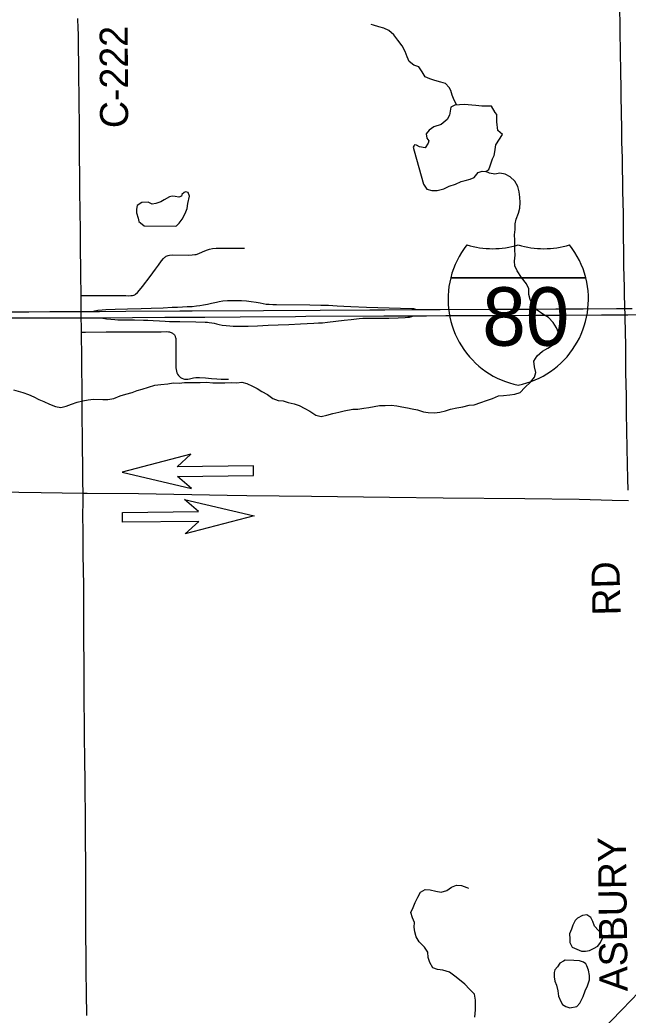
# Model space of a CAD drawing. Extents: x 0 to 34, y 0 to 22.
# Drawn here: x 10.62 to 13.7, y 14.41 to 19.45 of the extents above; entities that cross this region are included whole.
import ezdxf

# ---------------------------------------------------------------- set-up
doc = ezdxf.new("R2010")
doc.units = 0
for name, color, linetype in [('GM_X_County_Road', 7, 'Continuous'), ('GM_X_County_Road_Text', 7, 'Continuous'), ('GM_X_Interchange_Ramps', 7, 'Continuous'), ('GM_X_Interstate_Location', 7, 'Continuous'), ('GM_X_Interstate_Route', 7, 'Continuous'), ('GM_X_Interstate_Shield', 7, 'Continuous'), ('GM_X_Minor_Lake', 7, 'Continuous'), ('GM_X_Minor_River', 7, 'Continuous'), ('GM_X_State_Route', 7, 'Continuous'), ('GM_X_Township_Road', 7, 'Continuous'), ('PM_P_Cells', 7, 'Continuous')]:
    doc.layers.add(name, color=color, linetype=linetype)

msp = doc.modelspace()

# ---------------------------------------------------------------- linework, layer by layer
at = {"layer": 'GM_X_County_Road'}
for points in [[(13.7009, 17.0659), (13.6992, 17.1249), (13.6975, 17.1964), (13.6959, 17.2803), (13.6929, 17.4559), (13.6922, 17.5442), (13.6914, 17.6031), (13.6899, 17.6622), (13.6897, 17.7445), (13.6888, 17.7786), (13.6873, 17.8873), (13.6866, 17.9199), (13.6859, 17.9541), (13.6857, 17.9603), (13.6852, 17.9863), (13.6849, 18.0022), (13.6833, 18.0519), (13.6824, 18.0923), (13.6814, 18.1482), (13.6799, 18.2009), (13.6787, 18.246), (13.6776, 18.3797), (13.6769, 18.4667), (13.6743, 18.5801), (13.674, 18.636), (13.6724, 18.6872), (13.672, 18.7463), (13.6699, 18.8286), (13.6689, 18.883), (13.6668, 18.9902), (13.666, 19.0492), (13.6655, 19.0958), (13.6646, 19.189), (13.6623, 19.2806), (13.6605, 19.3909), (13.6595, 19.5338)], [(10.9342, 18.0514), (10.934, 18.0863), (10.9331, 18.1235), (10.9326, 18.1841), (10.9317, 18.2882), (10.9314, 18.3348), (10.9307, 18.4014), (10.9297, 18.4588), (10.9294, 18.4882), (10.9285, 18.5689), (10.9271, 18.6634), (10.9266, 18.7504), (10.9256, 18.8359), (10.9254, 18.8887), (10.9253, 18.9291), (10.9246, 19.013), (10.9236, 19.0876), (10.923, 19.1311), (10.9231, 19.1899), (10.9223, 19.2379), (10.9218, 19.2907), (10.9214, 19.3372), (10.9206, 19.3744), (10.9198, 19.4039), (10.9181, 19.4536)], [(10.9357, 17.8662), (10.9354, 17.8905), (10.9349, 17.9388), (10.9347, 17.971), (10.9346, 17.9884), (10.9342, 18.0514)], [(10.944, 17.0515), (10.9433, 17.1095), (10.9422, 17.198), (10.9415, 17.274), (10.9407, 17.3439), (10.9402, 17.4262), (10.9397, 17.4712), (10.9395, 17.5412), (10.9389, 17.6002), (10.9381, 17.667), (10.9375, 17.7183), (10.9371, 17.7617), (10.9362, 17.8361), (10.9357, 17.8662)], [(10.9629, 14.4078), (10.9624, 14.4295), (10.9615, 14.4978), (10.9611, 14.5475), (10.9605, 14.605), (10.9602, 14.6765), (10.9595, 14.7355), (10.9589, 14.7883), (10.9587, 14.8458), (10.9583, 14.9017), (10.9579, 14.9561), (10.9582, 15.0214), (10.9575, 15.11), (10.9576, 15.1628), (10.9576, 15.1876), (10.9565, 15.2839), (10.9563, 15.3477), (10.9562, 15.4362), (10.9548, 15.5341), (10.9542, 15.5963), (10.953, 15.6957), (10.9523, 15.7469), (10.9519, 15.7765), (10.9517, 15.8293), (10.9515, 15.8898), (10.9504, 15.9923), (10.9499, 16.0405), (10.9497, 16.1058), (10.9491, 16.2037), (10.9482, 16.2938), (10.948, 16.3637), (10.948, 16.4632), (10.9475, 16.5238), (10.9474, 16.5906), (10.946, 16.6558), (10.9454, 16.7459), (10.9451, 16.791), (10.9443, 16.8531), (10.9436, 16.9417), (10.9439, 17.0054), (10.944, 17.0515)]]:
    msp.add_lwpolyline(points, dxfattribs=at)
at = {"layer": 'GM_X_Interchange_Ramps'}
for points in [[(10.993, 17.9713), (11.0035, 17.9742), (11.0184, 17.9775), (11.0399, 17.9798), (11.059, 17.9812), (11.1057, 17.9825), (11.1693, 17.9842), (11.2372, 17.986), (11.2886, 17.9873), (11.3494, 17.99), (11.3951, 17.9919), (11.4215, 17.993), (11.4478, 17.9941), (11.4711, 17.9951), (11.4953, 17.9966), (11.5184, 17.9991), (11.5352, 18.0012), (11.5534, 18.0046), (11.5733, 18.0085), (11.5943, 18.013), (11.6185, 18.0183), (11.6324, 18.0214), (11.6503, 18.0238), (11.6741, 18.0256), (11.709, 18.0255), (11.7447, 18.0259), (11.7713, 18.0246), (11.7947, 18.0217), (11.8192, 18.0181), (11.8399, 18.0143), (11.8553, 18.0111), (11.8703, 18.0083), (11.886, 18.0069), (11.9035, 18.0062), (11.922, 18.006), (12.0913, 18.0047), (12.1472, 18.0035), (12.1847, 18.0022), (12.2294, 18.0001), (12.2635, 17.9982), (12.2992, 17.9962), (12.3784, 17.9928), (12.6064, 17.9865), (12.6114, 17.9861), (12.6153, 17.9855), (12.6198, 17.9844), (12.6255, 17.9828), (12.633, 17.9804)], [(11.0299, 17.9393), (11.0445, 17.9369), (11.0634, 17.9338), (11.0845, 17.9312), (11.1042, 17.9297), (11.1201, 17.9291), (11.1549, 17.9285), (11.2037, 17.9285), (11.2504, 17.9275), (11.2722, 17.9267), (11.2979, 17.9253), (11.3299, 17.9237), (11.3595, 17.9219), (11.3819, 17.9207), (11.4332, 17.9193), (11.5151, 17.918), (11.5613, 17.9167), (11.5727, 17.9159), (11.5815, 17.9151), (11.595, 17.913), (11.6072, 17.9109), (11.6184, 17.9083), (11.6327, 17.9052), (11.648, 17.9021), (11.6672, 17.8995), (11.6857, 17.8974), (11.7025, 17.8966), (11.7257, 17.8961), (11.7794, 17.8972), (11.8267, 17.8987), (11.8798, 17.9006), (11.9313, 17.9027), (11.9843, 17.9052), (12.0438, 17.9082), (12.1108, 17.9115), (12.1352, 17.9127), (12.1557, 17.914), (12.1804, 17.9161), (12.2654, 17.9263), (12.3009, 17.9303), (12.3409, 17.9347), (12.3591, 17.9363), (12.3721, 17.9368), (12.4006, 17.9371), (12.4248, 17.9372), (12.491, 17.9375), (12.5375, 17.9383), (12.5736, 17.9395), (12.5871, 17.9413), (12.5947, 17.9426), (12.6063, 17.946), (12.6156, 17.9487)]]:
    msp.add_lwpolyline(points, dxfattribs=at)
at = {"layer": 'GM_X_Interstate_Route'}
for points in [[(10.993, 17.9713), (11.0277, 17.9714), (11.1602, 17.9721), (11.433, 17.9736), (11.4964, 17.974), (11.8565, 17.9756), (12.1428, 17.9778), (12.3942, 17.9792), (12.4711, 17.9796), (12.633, 17.9804), (12.7495, 17.9804), (13.0075, 17.9818), (13.1481, 17.9825), (13.2237, 17.983), (13.3355, 17.9838), (13.4734, 17.9847), (13.6416, 17.9859), (13.6852, 17.9863), (13.7215, 17.9865)], [(7.4719, 17.9218), (7.5489, 17.9221), (7.6598, 17.9224), (7.7361, 17.9227), (8.0027, 17.9242), (8.0905, 17.9246), (8.2781, 17.9264), (8.3517, 17.9271), (8.5716, 17.9273), (8.9286, 17.9295), (9.0917, 17.9306), (9.2471, 17.9311), (9.406, 17.9317), (9.5726, 17.9321), (9.6848, 17.9327), (9.6918, 17.9328), (9.9166, 17.9339), (10.4286, 17.9381), (10.7084, 17.9392), (10.9328, 17.9387), (10.9349, 17.9388), (11.0299, 17.9393)], [(10.4796, 17.9683), (10.6702, 17.9694), (10.7762, 17.9701), (10.8983, 17.9708), (10.9347, 17.971), (10.993, 17.9713)], [(11.0299, 17.9393), (11.3584, 17.9414), (11.5599, 17.9427), (11.7385, 17.9439), (12.0183, 17.9459), (12.0715, 17.9463), (12.4647, 17.9481), (12.6156, 17.9487), (12.6805, 17.9488), (12.7784, 17.9497), (13.0435, 17.9511), (13.1956, 17.952), (13.3815, 17.9528), (13.5668, 17.9536), (13.6859, 17.9541), (13.7002, 17.9542), (13.8218, 17.9548)]]:
    msp.add_lwpolyline(points, dxfattribs=at)
at = {"layer": 'GM_X_Interstate_Shield'}
for p, q in [((12.8036, 18.1413), (13.4868, 18.1413)), ((13.4868, 18.1413), (12.8036, 18.1413)), ((13.4868, 18.1413), (12.8036, 18.1413))]:
    msp.add_line(p, q, dxfattribs=at)
for centre, start, end in [((13.234, 18.0325), 141.669, 165.8066), ((13.0155, 18.7323), 253.0091, 286.9909), ((13.2749, 18.7323), 253.0091, 286.9909), ((13.0564, 18.0325), 14.1934, 38.331), ((13.234, 18.0325), 165.8066, 258.463), ((13.0564, 18.0325), 281.537, 14.1934)]:
    msp.add_arc(centre, 0.4439, start, end, dxfattribs=at)
at = {"layer": 'GM_X_Minor_Lake'}
for p, q in [((12.6193, 18.7845), (12.6657, 18.6151)), ((11.2524, 18.4039), (11.4096, 18.4029)), ((13.4186, 14.7531), (13.4652, 14.7328)), ((13.4269, 14.6849), (13.3824, 14.6872))]:
    msp.add_line(p, q, dxfattribs=at)
for points in [[(12.6657, 18.6151), (12.683, 18.5897), (12.7077, 18.5833), (12.7351, 18.5827), (12.7691, 18.5917), (12.7964, 18.6053), (12.8285, 18.6151), (12.8568, 18.6288), (12.8775, 18.6337), (12.9021, 18.6397), (12.9219, 18.6494), (12.9424, 18.6734), (12.9632, 18.6803), (12.9812, 18.6786), (12.9972, 18.6902), (13.0036, 18.7074), (13.0155, 18.7426), (13.0229, 18.7598), (13.0265, 18.7788), (13.0318, 18.814), (13.0662, 18.8667), (13.0423, 18.8873), (13.0362, 18.9299), (13.0377, 18.967), (13.029, 18.9773), (13.0107, 19.0103), (12.9605, 19.0107), (12.9302, 19.0132), (12.8723, 19.0182), (12.8241, 19.0148), (12.8043, 19.0051), (12.7981, 18.9651), (12.7851, 18.9422), (12.7551, 18.9171), (12.7183, 18.9053), (12.6948, 18.888), (12.6799, 18.8697), (12.683, 18.8479), (12.6935, 18.8348), (12.6899, 18.8224), (12.675, 18.7994), (12.6456, 18.8048), (12.6303, 18.8131), (12.6208, 18.814), (12.618, 18.8111), (12.6134, 18.8016), (12.6193, 18.7845)], [(11.4096, 18.4029), (11.4162, 18.4049), (11.4303, 18.4183), (11.4452, 18.4375), (11.461, 18.4671), (11.4711, 18.4928), (11.4746, 18.5176), (11.4818, 18.5537), (11.4749, 18.5736), (11.4626, 18.5763), (11.4551, 18.5734), (11.4438, 18.5628), (11.442, 18.5552), (11.4288, 18.5493), (11.4098, 18.5529), (11.3956, 18.5537), (11.3814, 18.5516), (11.3541, 18.5361), (11.3382, 18.5264), (11.3127, 18.5166), (11.2928, 18.5145), (11.2729, 18.5237), (11.2407, 18.5224), (11.2172, 18.5079), (11.2145, 18.4889), (11.2147, 18.4708), (11.2226, 18.4434), (11.2266, 18.4263), (11.2352, 18.4188), (11.2524, 18.4039)], [(13.4652, 14.7328), (13.4861, 14.7321), (13.505, 14.7361), (13.5266, 14.7458), (13.5473, 14.7575), (13.5613, 14.7766), (13.5724, 14.8014), (13.5665, 14.8222), (13.5512, 14.8373), (13.531, 14.8598), (13.5232, 14.8834), (13.5116, 14.9033), (13.4916, 14.9163), (13.4699, 14.9132), (13.4454, 14.9006), (13.4332, 14.8881), (13.4221, 14.8652), (13.4148, 14.8442), (13.4037, 14.8203), (13.4068, 14.7947), (13.407, 14.7767), (13.4186, 14.7531)], [(13.3824, 14.6872), (13.3739, 14.6823), (13.3551, 14.6726), (13.344, 14.6535), (13.3299, 14.6381), (13.3263, 14.6248), (13.3265, 14.603), (13.3296, 14.5802), (13.3384, 14.5604), (13.3463, 14.532), (13.3484, 14.5054), (13.3601, 14.4781), (13.3688, 14.462), (13.386, 14.4527), (13.4059, 14.4463), (13.4409, 14.4524), (13.4568, 14.4697), (13.4744, 14.5031), (13.4835, 14.5327), (13.4956, 14.5565), (13.5057, 14.587), (13.5054, 14.6089), (13.5004, 14.6373), (13.4926, 14.659), (13.4877, 14.6685), (13.4753, 14.6778), (13.4554, 14.6842), (13.4269, 14.6849)]]:
    msp.add_lwpolyline(points, dxfattribs=at)
at = {"layer": 'GM_X_Minor_River'}
for points in [[(12.7966, 19.1047), (12.7777, 19.1241), (12.753, 19.1316), (12.7236, 19.1391), (12.6979, 19.1484), (12.6741, 19.1588), (12.6598, 19.1843), (12.6426, 19.209), (12.6179, 19.2183), (12.5932, 19.2363), (12.5826, 19.26), (12.573, 19.2875), (12.5577, 19.3159), (12.5357, 19.3434), (12.5157, 19.3718), (12.49, 19.3925), (12.4662, 19.4048), (12.4396, 19.4122), (12.4139, 19.4197), (12.4016, 19.4234)], [(12.8341, 19.0155), (12.821, 19.0404), (12.8112, 19.065), (12.8043, 19.0896), (12.7966, 19.1047)], [(11.9554, 17.5178), (11.981, 17.5105), (12.0123, 17.5033), (12.037, 17.4941), (12.0666, 17.4802), (12.0904, 17.4653), (12.1219, 17.4457), (12.1484, 17.4394), (12.1768, 17.4464), (12.207, 17.4543), (12.2372, 17.4613), (12.2646, 17.4673), (12.3081, 17.4764), (12.3336, 17.4767), (12.3648, 17.4808), (12.3903, 17.484), (12.4158, 17.49), (12.4433, 17.4941), (12.4716, 17.4954), (12.5029, 17.4967), (12.5304, 17.4923), (12.5569, 17.4878), (12.5845, 17.4834), (12.6082, 17.478), (12.6357, 17.4736), (12.6652, 17.4635), (12.6889, 17.4599), (12.7211, 17.4584), (12.7485, 17.4616), (12.7778, 17.4676), (12.8033, 17.4765), (12.8344, 17.4825), (12.8656, 17.4876), (12.8977, 17.4966), (12.9223, 17.4978), (12.9553, 17.5096), (12.9846, 17.5194), (13.0148, 17.5302), (13.0459, 17.5429), (13.0714, 17.5461), (13.1026, 17.5493), (13.1281, 17.5524), (13.1546, 17.5603), (13.178, 17.5862), (13.207, 17.6132), (13.2276, 17.6381), (13.2349, 17.6619), (13.227, 17.6912), (13.2238, 17.7197), (13.2415, 17.7465), (13.2687, 17.7705), (13.295, 17.7851), (13.3232, 17.8044), (13.3457, 17.8293), (13.352, 17.8551), (13.3384, 17.8872), (13.3211, 17.9154), (13.299, 17.9399), (13.2704, 17.9576), (13.2408, 17.9772), (13.2169, 18.0044), (13.2052, 18.0309), (13.1983, 18.0564), (13.1989, 18.0859), (13.1863, 18.1114), (13.1623, 18.1424), (13.1392, 18.1763), (13.1276, 18.2018), (13.1264, 18.2255), (13.1289, 18.2559), (13.1286, 18.2825), (13.1274, 18.3072), (13.128, 18.3319), (13.1268, 18.3585), (13.1293, 18.3851), (13.13, 18.4136), (13.1354, 18.4374), (13.1464, 18.4688), (13.1537, 18.4936), (13.1553, 18.523), (13.1531, 18.5487), (13.1499, 18.5771), (13.143, 18.6036), (13.1285, 18.631), (13.1046, 18.6516), (13.0798, 18.6665), (13.0523, 18.67), (13.0268, 18.6659), (12.9993, 18.6703), (12.9812, 18.6786)], [(10.5922, 17.5738), (10.6396, 17.5611), (10.6682, 17.551), (10.6948, 17.538), (10.7205, 17.526), (10.7462, 17.5149), (10.7748, 17.501), (10.8052, 17.4899), (10.8318, 17.4855), (10.8582, 17.4906), (10.8856, 17.5013), (10.9138, 17.5112), (10.9422, 17.5191), (10.9696, 17.5242), (10.997, 17.5264), (11.0434, 17.526), (11.0699, 17.5244), (11.0992, 17.5295), (11.1313, 17.5432), (11.1605, 17.5521), (11.1917, 17.561), (11.2181, 17.5708), (11.2426, 17.5777), (11.2757, 17.5876), (11.3077, 17.5985), (11.3371, 17.6017), (11.3721, 17.604), (11.4004, 17.609), (11.4298, 17.6075), (11.4572, 17.6116), (11.4818, 17.611), (11.5358, 17.6116), (11.568, 17.6129), (11.6002, 17.6095), (11.6258, 17.6098), (11.6617, 17.6093), (11.6949, 17.6106), (11.7224, 17.6091), (11.7479, 17.6132), (11.7726, 17.6068), (11.8011, 17.5919), (11.8249, 17.5808), (11.8488, 17.5659), (11.8773, 17.5501), (11.9041, 17.5305), (11.9307, 17.5194), (11.9554, 17.5178)], [(12.9254, 14.398), (12.9288, 14.435), (12.9283, 14.4853), (12.9232, 14.5147), (12.8992, 14.541), (12.8753, 14.5654), (12.8476, 14.5879), (12.8237, 14.6066), (12.797, 14.6272), (12.7637, 14.6372), (12.7372, 14.6398), (12.7134, 14.649), (12.6989, 14.6754), (12.6892, 14.7), (12.6879, 14.7275), (12.6706, 14.7529), (12.6447, 14.7802), (12.6293, 14.8056), (12.6214, 14.8302), (12.6193, 14.8539), (12.62, 14.8776), (12.6112, 14.9022), (12.6024, 14.9287), (12.6144, 14.9535), (12.6245, 14.9783), (12.6375, 15.006), (12.6505, 15.0309), (12.6749, 15.0444), (12.7005, 15.0428), (12.729, 15.0365), (12.7556, 15.0321), (12.7839, 15.04), (12.8083, 15.0564), (12.8328, 15.0662), (12.8584, 15.0646), (12.885, 15.0554), (12.8936, 15.0518)]]:
    msp.add_lwpolyline(points, dxfattribs=at)
at = {"layer": 'GM_X_State_Route'}
for points in [[(10.3908, 17.0589), (10.7326, 17.0543), (10.944, 17.0515), (10.9641, 17.0512), (11.2251, 17.0488), (11.6738, 17.0415), (11.7717, 17.0395), (12.0995, 17.036), (12.4942, 17.0313), (12.7661, 17.0273), (13.178, 17.0239), (13.453, 17.02), (13.6208, 17.016), (13.7026, 17.0131)], [(13.4993, 14.2609), (13.671, 14.4383), (13.7555, 14.5258), (13.9625, 14.7401), (14.2036, 14.9913), (14.4144, 15.2089), (14.5928, 15.3952), (14.8657, 15.678), (15.0774, 15.897), (15.1208, 15.9421)]]:
    msp.add_lwpolyline(points, dxfattribs=at)
at = {"layer": 'GM_X_Township_Road'}
for points in [[(10.9342, 18.0514), (10.9557, 18.0514), (11.0411, 18.0513), (11.1126, 18.051), (11.1607, 18.0508), (11.1716, 18.0506), (11.1854, 18.0509), (11.1937, 18.0517), (11.2001, 18.0534), (11.2055, 18.0556), (11.2095, 18.0581), (11.2196, 18.0666), (11.2298, 18.078), (11.2449, 18.0976), (11.2833, 18.1484), (11.3103, 18.1845), (11.3251, 18.2045), (11.3416, 18.2271), (11.3505, 18.2382), (11.3574, 18.2449), (11.3611, 18.2479), (11.3648, 18.2506), (11.3691, 18.2531), (11.3741, 18.2548), (11.382, 18.2562), (11.3978, 18.2571), (11.4756, 18.2563), (11.4956, 18.2571), (11.5099, 18.2583), (11.516, 18.2597), (11.5298, 18.2646), (11.5481, 18.2725), (11.5681, 18.2813), (11.583, 18.2864), (11.5985, 18.2896), (11.6173, 18.2909), (11.6811, 18.2919), (11.76, 18.2916)], [(10.9357, 17.8662), (10.9562, 17.8664), (11.0603, 17.8672), (11.135, 17.8674), (11.1738, 17.8674), (11.2345, 17.8671), (11.3387, 17.8684), (11.3638, 17.8686), (11.3757, 17.868), (11.3807, 17.8673), (11.3852, 17.8664), (11.3895, 17.865), (11.3935, 17.8632), (11.3973, 17.8608), (11.4006, 17.8583), (11.4036, 17.8551), (11.4058, 17.8523), (11.4076, 17.8498), (11.4094, 17.8465), (11.4107, 17.8426), (11.4119, 17.8387), (11.413, 17.8345), (11.4136, 17.8295), (11.4141, 17.8175), (11.4141, 17.8033), (11.4138, 17.7104), (11.4139, 17.6857), (11.4145, 17.6763), (11.416, 17.6688), (11.419, 17.6603), (11.4223, 17.6535), (11.4272, 17.646), (11.4312, 17.6417), (11.4368, 17.6369), (11.4445, 17.6325), (11.4515, 17.6299), (11.4576, 17.6283), (11.4655, 17.6275), (11.4733, 17.6279), (11.4823, 17.6296), (11.4962, 17.6339), (11.5023, 17.6349), (11.5149, 17.6363), (11.5322, 17.636), (11.5634, 17.6344), (11.5945, 17.6317), (11.6207, 17.6291), (11.6424, 17.6279), (11.6655, 17.6281), (11.6795, 17.6287)]]:
    msp.add_lwpolyline(points, dxfattribs=at)
at = {"layer": 'PM_P_Cells'}
for p, q in [((11.49, 17.2478), (11.1411, 17.1566)), ((11.4208, 17.1851), (11.49, 17.2478)), ((11.8058, 17.19), (11.4208, 17.1851)), ((11.8064, 17.14), (11.8058, 17.19)), ((11.1411, 17.1566), (11.1411, 17.1566)), ((11.1411, 17.1566), (11.4922, 17.0742)), ((11.4214, 17.1351), (11.8064, 17.14)), ((11.4922, 17.0742), (11.4214, 17.1351)), ((11.8061, 17.165), (11.8061, 17.165)), ((11.5287, 16.9584), (11.4579, 17.0194)), ((11.4579, 17.0194), (11.809, 16.937)), ((11.1437, 16.9536), (11.5287, 16.9584)), ((11.1444, 16.9036), (11.1437, 16.9536)), ((11.144, 16.9286), (11.144, 16.9286)), ((11.809, 16.937), (11.4601, 16.8458)), ((11.809, 16.937), (11.809, 16.937)), ((11.5293, 16.9084), (11.1444, 16.9036)), ((11.4601, 16.8458), (11.5293, 16.9084))]:
    msp.add_line(p, q, dxfattribs=at)

# ---------------------------------------------------------------- texts
at = {"layer": 'GM_X_County_Road_Text'}
for s, rotation, p in [('C-222', 90.2739, (11.1723, 18.8991)), ('RD', 91.4825, (13.6633, 16.4335)), ('ASBURY', 90.6776, (13.6987, 14.5299))]:
    msp.add_text(s, height=0.14205, rotation=rotation, dxfattribs=at).set_placement(p)
at = {"layer": 'GM_X_Interstate_Location'}
for s in ['-', '.', ',']:
    msp.add_text(s, height=0.000473, dxfattribs=at).set_placement((13.1451, 17.9524))
msp.add_text('80', height=0.000473, rotation=0, dxfattribs=at).set_placement((13.0484, 17.8544))
at = {"layer": 'GM_X_Interstate_Shield'}
msp.add_text('80', height=0.29593, dxfattribs=at).set_placement((12.9633, 17.7973))

doc.saveas('drawing.dxf')
